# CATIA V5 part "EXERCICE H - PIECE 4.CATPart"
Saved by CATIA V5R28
Part number: EXERCICE H - PIECE 4
Bounding box of the stored display mesh (mm): x -12 to 0, y -6 to 6, z 0 to 18
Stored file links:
  \\stisrv.epfl.ch\sti-sgm\sgm-ens\soubiell\Enseignement\ME-101-106 - Construction Mécanique I\1. Supports de cours\Z. Archives\2020\SW3\Modèles 3D exercice H\EXERCICE H - PIECE 4.CATPart
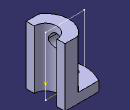
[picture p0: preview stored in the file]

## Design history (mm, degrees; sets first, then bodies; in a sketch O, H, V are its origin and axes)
Body1 (main body)
  Sketch1 on xy-plane, origin (0, 0, 0), H (1, 0, 0), V (0, 1, 0)
    arc A1 centre (0, 0) radius 3.5 from (0, 3.5) to (0, -3.5) ccw
    line L1 (0, -3.5) -> (0, -6)
    point P3 (0, -6)
    line L2 (0, 3.5) -> (0, 6)
    line L3 (0, 6) -> (-10.3923, 6)
    point P6 (-10.3923, 6)
    arc A2 centre (0, 0) radius 12 from (-10.3923, 6) to (-10.3923, -6) ccw
    point P7 (-10.3923, 6)
    reference intersected line E1 through (0, 0) direction (0, 1) from yz-plane
    line L4 (0, -6) -> (-10.3923, -6)
    radius A1 = 3.5
    radius A2 = 12
    distance H L3 = 6
    distance P3 H = 6
    coincidence: P6 P7, L2 L1, E1 L1
    perpendicularity: L3 L2
    horizontal: L4 H
  Pad1: profile Sketch1, direction (0, 0, 1), length 3
  Sketch2 on end face of Pad1, origin (0, 0, 3), H (1, 0, 0), V (0, 1, 0)
    projected line E1 (0, -6) -> (0, -3.5) from edge [face of Pad1 from Sketch1.L1 | end face of Pad1]
    projected arc E2 centre (0, 0) radius 3.5 from (0, 3.5) to (0, -3.5) ccw from edge [face of Pad1 from Sketch1.A1 | end face of Pad1]
    projected line E3 (0, 3.5) -> (0, 6) from edge [face of Pad1 from Sketch1.L2 | end face of Pad1]
    arc A1 centre (0, 0) radius 7.2 from (-3.9799, 6) to (-3.9799, -6) ccw
    line L1 (-3.9799, 6) -> (0, 6)
    line L2 (-3.9799, -6) -> (0, -6)
    radius A1 = 7.2
    horizontal: L2 H, L1 H
  Pad2: profile Sketch2, direction (0, 0, 1), length 15
  Sketch3 on end face of Pad1, origin (-9.7241, 2.311, 3), H (1, 0, 0), V (0, 1, 0)
    point P1 (0.7241, -2.311)
    reference intersected line E1 through (0, -2.311) direction (-1, 0) from zx-plane
    reference intersected line E2 through (9.7241, 0) direction (0, 1) from yz-plane
    distance P1 E2 = 9
    coincidence: P1 E1
  Hole1: placed by Sketch3, at (-9, 0, 3) direction (0, 0, -1), diameter 2, through (limit type 6)
  Sketch4 on yz-plane, origin (0, 0, 0), H (0, 1, 0), V (0, 0, 1)
    circle A1 centre (0, 14) radius 2
    point P1 (0, 14)
    distance P1 H = 14
    radius A1 = 2
    coincidence: P1 V
  Pocket1: profile Sketch4, direction (-1, 0, 0), through (limit type 6)
  Sketch5 "PLAN DE COUPE D-D" on zx-plane, origin (0, 0, 0), H (-1, 0, 0), V (0, 0, 1)
    line L1 (0, 0) -> (12, 0)
    line L2 (12, 0) -> (12, 18)
    line L3 (12, 18) -> (0, 18)
    line L4 (0, 18) -> (0, 0)
    length L2 = 18
    length L3 = 12
    horizontal: L1 H, L3 H
    vertical: L2 V, L4 V
  Pocket2 "COUPE D-D": profile Sketch5, direction (0, -1, 0), through (limit type 6)
Current feature: Pocket1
